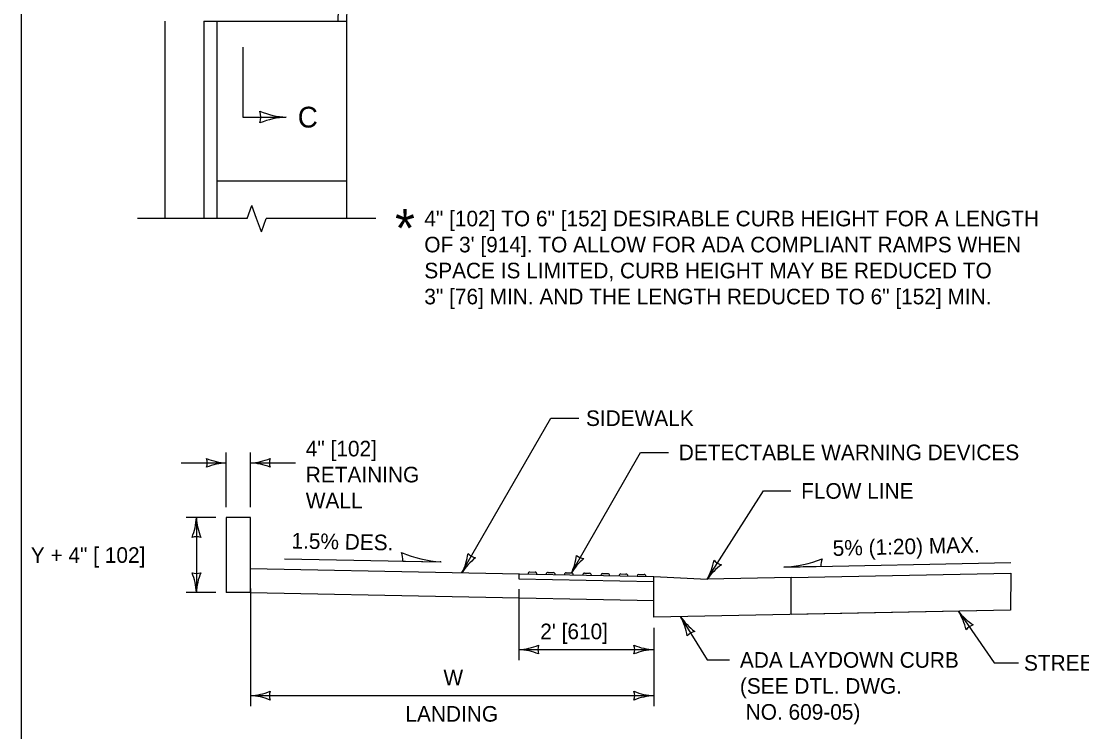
# Model space of a CAD drawing. Extents: x 49991.4 to 50021, y 49987.6 to 50011.4.
# Drawn here: x 50000.336 to 50004.419, y 50005.18 to 50007.914 of the extents above; entities that cross this region are included whole.
import ezdxf

# ---------------------------------------------------------------- set-up
doc = ezdxf.new("R2010")
doc.units = 0
for name, color, linetype in [('Level 1', 7, 'Continuous'), ('Level 2', 7, 'Continuous'), ('Level 3', 7, 'Continuous'), ('Level 6', 7, 'Continuous')]:
    doc.layers.add(name, color=color, linetype=linetype)

msp = doc.modelspace()

# ---------------------------------------------------------------- linework, layer by layer
at = {"layer": 'Level 1'}
for p, q in [((50000.8885, 50007.9136), (50000.8885, 50007.1544)), ((50001.0385, 50007.9137), (50001.5885, 50007.9135)), ((50001.0385, 50007.9136), (50001.0385, 50007.1544)), ((50001.0885, 50007.9136), (50001.0885, 50007.1544)), ((50001.5885, 50007.9136), (50001.5885, 50007.1544)), ((50001.0885, 50007.3001), (50001.5885, 50007.3001)), ((50001.1252, 50006.0038), (50001.1252, 50005.7156)), ((50001.2178, 50006.0038), (50001.1252, 50006.0038)), ((50001.2178, 50005.7156), (50001.2178, 50006.0038)), ((50001.2178, 50005.8082), (50002.7709, 50005.7772)), ((50002.294, 50005.7945), (50002.314, 50005.7941)), ((50002.364, 50005.793), (50002.384, 50005.7926)), ((50002.434, 50005.7915), (50002.454, 50005.7911)), ((50002.504, 50005.79), (50002.524, 50005.7896)), ((50002.5739, 50005.7885), (50002.5939, 50005.7881)), ((50002.6439, 50005.787), (50002.6639, 50005.7866)), ((50002.7139, 50005.7855), (50002.7339, 50005.7851)), ((50002.7709, 50005.6202), (50002.7709, 50005.7772)), ((50002.7709, 50005.7772), (50002.9765, 50005.767)), ((50003.2999, 50005.7735), (50002.9765, 50005.767)), ((50003.2999, 50005.7735), (50004.1454, 50005.7906)), ((50003.2999, 50005.6309), (50003.2999, 50005.7735)), ((50004.1454, 50005.7906), (50004.1449, 50005.648)), ((50001.2178, 50005.7156), (50001.1252, 50005.7156)), ((50001.2178, 50005.7156), (50002.7709, 50005.6846)), ((50004.1449, 50005.648), (50002.7709, 50005.6202)), ((50004.1449, 50005.648), (50003.2999, 50005.6309))]:
    msp.add_line(p, q, dxfattribs=at)
msp.add_lwpolyline([(50008.6146, 50011.2628), (50000.3356, 50011.2628), (50000.3356, 50000.0624), (50008.6146, 50000.0624)], close=True, dxfattribs=at)
for points in [[(50000.3356, 50011.2628), (50000.3356, 50000.0624)], [(50002.2514, 50005.7876), (50002.2514, 50005.7681), (50002.7705, 50005.7577)]]:
    msp.add_lwpolyline(points, dxfattribs=at)
for centre, radius, start, end in [((50003.5885, 50007.9135), 2, 89.9972, 179.9963), ((50003.5885, 50007.9135), 2.0333, 140.0675, 179.9963), ((50002.294, 50005.7873), 0.00718, 90.1339, 183.3533), ((50002.3139, 50005.7869), 0.00715, 354.3102, 89.0798), ((50002.364, 50005.7858), 0.00718, 90.1339, 182.5606), ((50002.3839, 50005.7854), 0.00715, 355.1065, 89.0798), ((50002.434, 50005.7843), 0.00718, 90.1339, 181.7686), ((50002.4539, 50005.7839), 0.00715, 355.902, 89.0798), ((50002.504, 50005.7828), 0.00718, 90.1339, 180.9772), ((50002.5238, 50005.7824), 0.00715, 356.6969, 89.0798), ((50002.574, 50005.7813), 0.00718, 90.1339, 178.2185), ((50002.5938, 50005.7809), 0.00715, 359.0798, 89.0798), ((50002.6439, 50005.7798), 0.00718, 90.1339, 179.3955), ((50002.6638, 50005.7794), 0.00715, 358.2857, 89.0798), ((50002.7139, 50005.7783), 0.00718, 90.1339, 178.6048), ((50002.7338, 50005.7779), 0.00715, 359.0798, 89.0798)]:
    msp.add_arc(centre, radius, start, end, dxfattribs=at)
at = {"layer": 'Level 3'}
for p, q in [((50002.0324, 50005.792), (50002.374, 50006.3863)), ((50002.374, 50006.3863), (50002.4819, 50006.3863)), ((50001.1252, 50006.0438), (50001.1252, 50006.2543)), ((50001.2178, 50006.0438), (50001.2178, 50006.2543)), ((50002.72, 50006.2547), (50002.8272, 50006.2547)), ((50000.9517, 50006.2143), (50001.1252, 50006.2143)), ((50001.2178, 50006.2143), (50001.3912, 50006.2143)), ((50002.9765, 50005.767), (50003.1929, 50006.1064)), ((50003.1929, 50006.1064), (50003.2983, 50006.1064)), ((50001.0852, 50006.0038), (50000.9701, 50006.0038)), ((50001.0101, 50006.0038), (50001.0101, 50005.7156)), ((50001.3489, 50005.8456), (50001.9487, 50005.8336)), ((50003.2722, 50005.8126), (50004.1454, 50005.8309)), ((50001.0852, 50005.7156), (50000.9701, 50005.7156)), ((50001.2178, 50005.7304), (50001.2178, 50005.2787)), ((50002.2514, 50005.7281), (50002.2514, 50005.4559)), ((50003.9436, 50005.6439), (50004.0819, 50005.4449)), ((50002.8744, 50005.6223), (50002.9761, 50005.4561)), ((50002.7709, 50005.5801), (50002.7709, 50005.2787)), ((50002.2514, 50005.4959), (50002.7709, 50005.4959)), ((50002.9761, 50005.4561), (50003.0625, 50005.4561)), ((50004.0819, 50005.4449), (50004.1757, 50005.4449)), ((50001.2178, 50005.3187), (50002.7709, 50005.3187))]:
    msp.add_line(p, q, dxfattribs=at)
for points in [[(50002.454, 50005.7911), (50002.72, 50006.2547)], [(50001.8049, 50005.8365), (50001.9487, 50005.8336)], [(50003.4143, 50005.8154), (50003.2768, 50005.8125)]]:
    msp.add_lwpolyline(points, dxfattribs=at)
for centre, radius, start, end in [((50001.1853, 50007.5446), 0.073, 342.1388, 17.8612), ((50001.3715, 50007.8549), 0.3107, 247.9228, 267.1727), ((50001.3684, 50007.2485), 0.2964, 92.3605, 112.544), ((50001.1343, 50006.4364), 0.2223, 247.456, 267.6395), ((50000.9969, 50006.2143), 0.0548, 342.1388, 17.8612), ((50001.1366, 50005.9816), 0.233, 92.8273, 112.0772), ((50001.2063, 50006.447), 0.233, 272.8273, 292.0772), ((50001.2086, 50005.9922), 0.2223, 67.456, 87.6395), ((50001.346, 50006.2143), 0.0548, 162.1388, 197.8612), ((50000.7879, 50006.013), 0.2223, 337.456, 357.6395), ((50001.2428, 50006.0153), 0.233, 182.8273, 202.0772), ((50001.0101, 50005.8756), 0.0548, 72.1388, 107.8612), ((50001.9769, 50006.2777), 0.4446, 246.5772, 266.7607), ((50001.6954, 50005.8377), 0.1095, 359.3823, 16.9823), ((50001.8353, 50005.8947), 0.2223, 332.4723, 352.6559), ((50002.2285, 50005.666), 0.233, 128.0347, 147.2846), ((50002.0963, 50005.9031), 0.0548, 222.2507, 257.973), ((50002.774, 50005.8823), 0.233, 330.3226, 349.5725), ((50003.0454, 50005.8751), 0.0548, 219.6341, 255.3565), ((50001.9676, 50005.368), 0.466, 91.9485, 92.3326), ((50003.1589, 50005.6399), 0.2223, 124.9513, 145.1348), ((50001.0101, 50005.8438), 0.0548, 252.1388, 287.8612), ((50000.7773, 50005.7041), 0.233, 2.8273, 22.0772), ((50001.2322, 50005.7065), 0.2223, 157.456, 177.6395), ((50004.1206, 50005.7784), 0.2223, 217.2393, 237.4228), ((50003.7461, 50005.5203), 0.233, 12.8017, 32.0515), ((50002.6801, 50005.514), 0.2223, 8.9423, 29.1258), ((50003.0668, 50005.7536), 0.233, 214.3136, 233.5634), ((50004.0169, 50005.5387), 0.0548, 107.0177, 142.74), ((50002.9413, 50005.5129), 0.0548, 103.6251, 139.3474), ((50002.2399, 50005.7286), 0.233, 272.8273, 292.0772), ((50002.3796, 50005.4959), 0.0548, 162.1388, 197.8612), ((50002.78, 50005.7181), 0.2223, 247.456, 267.6395), ((50002.6426, 50005.4959), 0.0548, 342.1388, 17.8612), ((50002.2422, 50005.2738), 0.2223, 67.456, 87.6395), ((50002.7823, 50005.2632), 0.233, 92.8273, 112.0772), ((50001.2062, 50005.5514), 0.233, 272.8273, 292.0772), ((50001.2086, 50005.0966), 0.2223, 67.456, 87.6395), ((50001.3459, 50005.3187), 0.0548, 162.1388, 197.8612), ((50002.78, 50005.5408), 0.2223, 247.456, 267.6395), ((50002.6426, 50005.3187), 0.0548, 342.1388, 17.8612), ((50002.7823, 50005.086), 0.233, 92.8273, 112.0772)]:
    msp.add_arc(centre, radius, start, end, dxfattribs=at)
for centre, major_axis, start_param, end_param in [((50002.2492, 50005.8681), (0.2203, 0.0484), 5.662673, 5.998647), ((50002.6406, 50005.7013), (-0.2102, -0.0462), 5.219861, 5.572129), ((50002.5103, 50005.894), (-0.0518, -0.0114), 0.589202, 1.212675), ((50003.246, 50006.2031), (0.4303, 0.0093), 4.753587, 5.105856), ((50003.5204, 50005.818), (-0.106, -0.0023), 5.971449, 6.286608), ((50003.2588, 50005.4027), (0.451, 0.0098), 1.511189, 1.52145)]:
    msp.add_ellipse(centre, major_axis=major_axis, ratio=0.909091, start_param=start_param, end_param=end_param, dxfattribs=at)
at = {"layer": 'Level 6'}
for p, q in [((50001.1885, 50007.8136), (50001.1885, 50007.6303)), ((50001.1885, 50007.7279), (50001.1885, 50007.5446)), ((50001.1885, 50007.5446), (50001.3562, 50007.5446)), ((50001.1885, 50007.5446), (50001.3562, 50007.5446)), ((50001.2058, 50007.1544), (50001.224, 50007.2052)), ((50001.242, 50007.1544), (50001.224, 50007.2052)), ((50001.2058, 50007.1544), (50000.7837, 50007.1544)), ((50001.2601, 50007.1034), (50001.242, 50007.1544)), ((50001.2601, 50007.1034), (50001.2781, 50007.1544)), ((50001.7007, 50007.1544), (50001.2781, 50007.1544))]:
    msp.add_line(p, q, dxfattribs=at)

# ---------------------------------------------------------------- texts
at = {"layer": 'Level 2'}
for s, height, p in [('C', 0.08, (50001.4003, 50007.5046)), ('4" [102] TO 6" [152] DESIRABLE CURB HEIGHT FOR A LENGTH', 0.06, (50001.8875, 50007.1245)), ("OF 3' [914]. TO ALLOW FOR ADA COMPLIANT RAMPS WHEN", 0.06, (50001.8875, 50007.0244)), ('SPACE IS LIMITED, CURB HEIGHT MAY BE REDUCED TO', 0.06, (50001.8875, 50006.9244)), ('3" [76] MIN. AND THE LENGTH REDUCED TO 6" [152] MIN.', 0.06, (50001.8875, 50006.8244)), ('SIDEWALK', 0.06, (50002.51, 50006.3563)), ('4" [102] ', 0.06, (50001.4312, 50006.2393)), ('DETECTABLE WARNING DEVICES', 0.06, (50002.8672, 50006.2247)), ('RETAINING', 0.06, (50001.4312, 50006.1393)), ('FLOW LINE', 0.06, (50003.3383, 50006.0764)), ('WALL', 0.06, (50001.4312, 50006.0393)), ('Y + 4" [ 102]', 0.06, (50000.3725, 50005.8297)), ("2' [610]", 0.06, (50002.3339, 50005.5359)), ('ADA LAYDOWN CURB', 0.06, (50003.1025, 50005.4261)), ('STREET', 0.06, (50004.1962, 50005.4149)), ('W', 0.06, (50001.9612, 50005.3587)), ('(SEE DTL. DWG.', 0.06, (50003.1025, 50005.3261)), ('LANDING', 0.06, (50001.8148, 50005.2187)), (' NO. 609-05)', 0.06, (50003.1025, 50005.2261))]:
    msp.add_text(s, height=height, dxfattribs=at).set_placement(p)
for s, rotation, p in [('1.5% DES.', 358.8565, (50001.3756, 50005.8851)), ('5% (1:20) MAX.', 1.3967, (50003.4604, 50005.8561))]:
    msp.add_text(s, height=0.06, rotation=rotation, dxfattribs=at).set_placement(p)
at = {"layer": 'Level 3'}
msp.add_text('*', height=0.147, rotation=360, dxfattribs=at).set_placement((50001.7748, 50007.0442))

doc.saveas('drawing.dxf')
